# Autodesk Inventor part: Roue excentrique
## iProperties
Shininess: 20.0
Length Units: 11269
Angle Units: 11279
Time Units: 11290
Mass Units: 11283
Length Display Precision: 3
Angle Display Precision: 2
Created: 2002-05
Part Number: Roue excentrique
Material: Par défaut
Document SubType Name: Modélisation
Designer: Flavien MARTY
Density: 0.0
Volumn: 0.0
Area: 0.0
PropertySet Name: Model Information
Control State: 0
Master: False
Checked Out: False
Author: Flavien MARTY
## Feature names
1. Extrusion1
2. Extrusion2
3. Perçage1 [Hole]
4. Excentrique [Extrusion]
5. Congé1 [Fillet]
